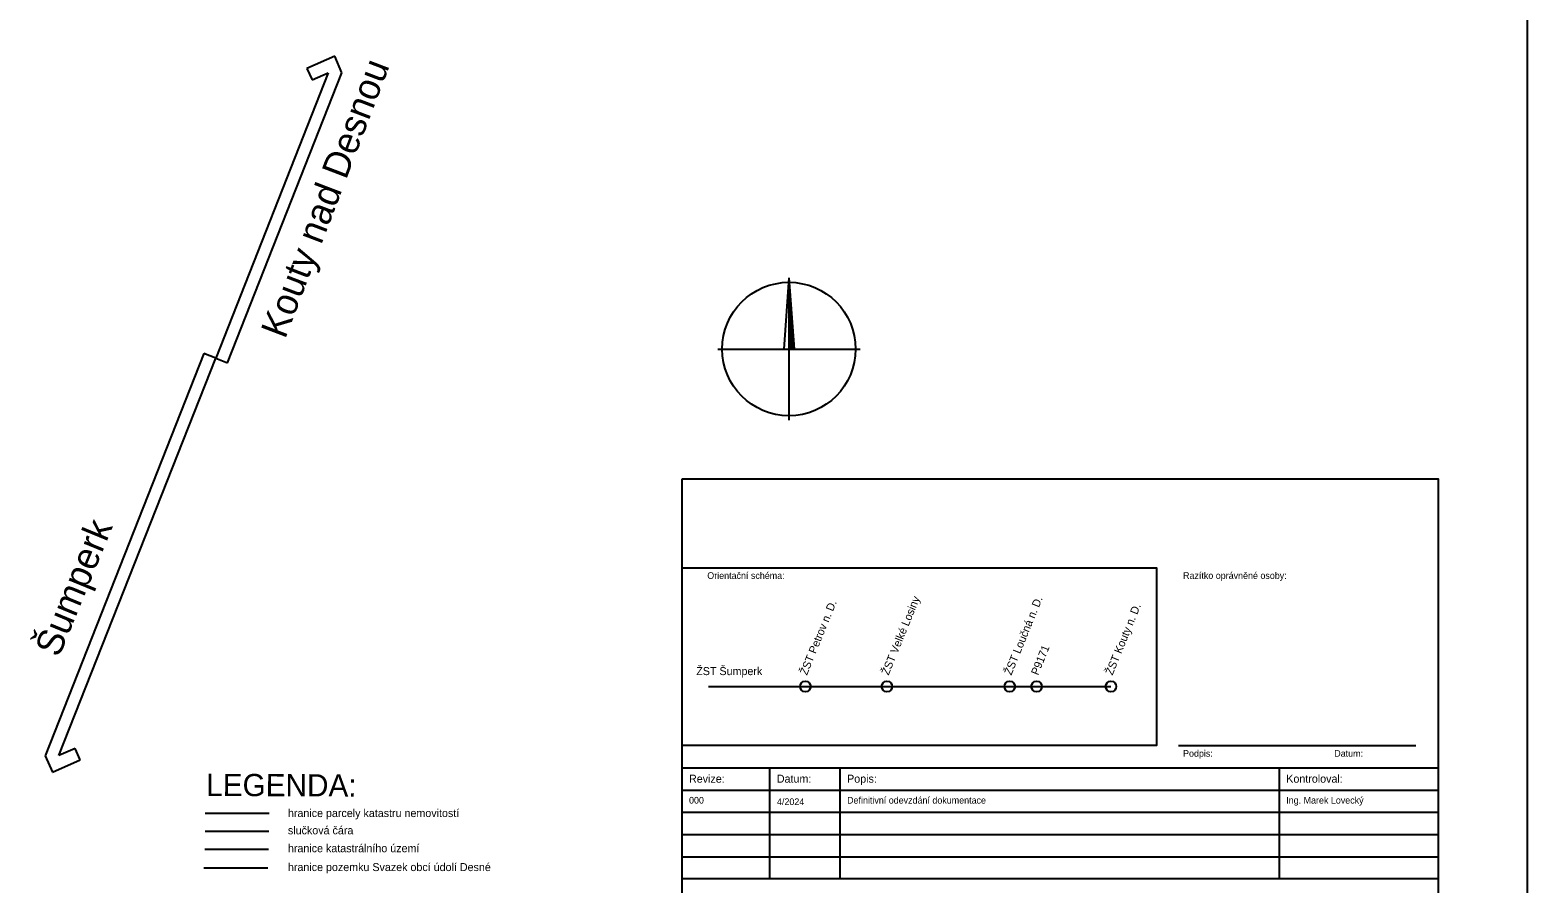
# Model space of a CAD drawing. Extents: x -553916 to -552953, y -1067470 to -1066637.
# Drawn here: x -553289.8 to -552953.1, y -1067224.2 to -1067032.3 of the extents above; entities that cross this region are included whole.
import ezdxf

# ---------------------------------------------------------------- set-up
doc = ezdxf.new("R2010")
doc.units = 0
for name, color, linetype in [('ROZPISKA', 7, 'Continuous'), ('Rozpiska_pola_3', 7, 'Continuous'), ('Rozpiska_pole_1', 7, 'Continuous'), ('Rozpiska_pole_2', 7, 'Continuous'), ('Rozpiska_pole_4', 7, 'Continuous'), ('Rozpiska_pole_6', 7, 'Continuous'), ('Rozpiska_pole_7', 7, 'Continuous'), ('Vrstva 1', 7, 'Continuous')]:
    doc.layers.add(name, color=color, linetype=linetype)

# ---------------------------------------------------------------- blocks, each defined once
blk = doc.blocks.new('_U2')
at = {"layer": 'Rozpiska_pola_3'}
blk.add_line((-2.6675, -1.82505), (2.6675, -1.82505), dxfattribs=at)
for s, p in [('Razítko oprávněné osoby:', (-2.5675, 1.92495)), ('Podpis:', (-2.5675, -2.07505)), ('Datum:', (0.8325, -2.07505))]:
    blk.add_text(s, height=0.15, dxfattribs=at).set_placement(p)
blk = doc.blocks.new('_U3')
at = {"layer": 'Rozpiska_pole_2'}
blk.add_lwpolyline([(-5.33255, 2.00005), (5.33245, 2.00005), (5.33245, -1.99995), (-5.33255, -1.99995)], close=True, dxfattribs=at)
blk.add_text('Orientační schéma:', height=0.15, dxfattribs=at).set_placement((-4.76755, 1.75005))

msp = doc.modelspace()

# ---------------------------------------------------------------- linework, layer by layer
at = {"layer": 'ROZPISKA'}
msp.add_lwpolyline([(-553137.18, -1067179.97), (-553046.68, -1067179.97)], dxfattribs=at)
for centre in [(-553115.39, -1067179.97), (-553097.05, -1067179.97), (-553069.44, -1067179.97), (-553063.4, -1067179.97), (-553046.68, -1067179.97), (-553046.68, -1067179.97), (-553046.68, -1067179.97), (-553046.68, -1067179.97)]:
    msp.add_circle(centre, 1.2, dxfattribs=at)
at = {"layer": 'Rozpiska_pole_1'}
msp.add_lwpolyline([(-553143.11, -1067133.27), (-552973.11, -1067133.27), (-552973.11, -1067393.27), (-553143.11, -1067393.27)], close=True, dxfattribs=at)
at = {"layer": 'Rozpiska_pole_4'}
for p, q in [((-553123.36, -1067223.27), (-553123.36, -1067198.27)), ((-553107.56, -1067223.27), (-553107.56, -1067198.27)), ((-553008.81, -1067223.27), (-553008.81, -1067198.27)), ((-553143.11, -1067203.27), (-552973.11, -1067203.27)), ((-553143.11, -1067208.27), (-552973.11, -1067208.27)), ((-553143.11, -1067213.27), (-552973.11, -1067213.27)), ((-553143.11, -1067218.27), (-552973.11, -1067218.27))]:
    msp.add_line(p, q, dxfattribs=at)
msp.add_lwpolyline([(-553143.11, -1067198.27), (-552973.11, -1067198.27), (-552973.11, -1067223.27), (-553143.11, -1067223.27)], close=True, dxfattribs=at)
at = {"layer": 'Vrstva 1'}
for p, q in [((-552953.11, -1066816.27), (-552953.11, -1067410.27)), ((-553221.23, -1067038.23), (-553227.51, -1067040.96)), ((-553219.64, -1067041.91), (-553221.23, -1067038.23)), ((-553222.7, -1067041.96), (-553248, -1067106.1)), ((-553245.37, -1067107.14), (-553219.64, -1067041.91)), ((-553227.51, -1067040.96), (-553226.33, -1067043.54)), ((-553226.33, -1067043.54), (-553222.7, -1067041.96)), ((-553119.1, -1067088.06), (-553120.25, -1067104.06)), ((-553119.1, -1067088.06), (-553117.93, -1067104.06)), ((-553119.1, -1067088.06), (-553119.1, -1067120.06)), ((-553119.01, -1067090.3), (-553118.03, -1067103.96)), ((-553118.97, -1067103.92), (-553119.01, -1067090.3)), ((-553118.94, -1067092.53), (-553118.14, -1067103.89)), ((-553118.87, -1067103.82), (-553118.94, -1067092.53)), ((-553118.83, -1067095.11), (-553118.24, -1067103.75)), ((-553118.8, -1067103.75), (-553118.83, -1067095.11)), ((-553118.73, -1067097.79), (-553118.35, -1067103.64)), ((-553118.69, -1067103.68), (-553118.73, -1067097.79)), ((-553135.1, -1067104.06), (-553103.1, -1067104.06)), ((-553117.93, -1067104.06), (-553118.97, -1067103.92)), ((-553118.03, -1067103.96), (-553118.87, -1067103.82)), ((-553118.14, -1067103.89), (-553118.8, -1067103.75)), ((-553118.24, -1067103.75), (-553118.69, -1067103.68)), ((-553118.59, -1067100.79), (-553118.45, -1067103.47)), ((-553118.59, -1067103.57), (-553118.59, -1067100.79)), ((-553118.35, -1067103.64), (-553118.59, -1067103.57)), ((-553250.64, -1067105.06), (-553286.33, -1067195.54)), ((-553283.26, -1067195.49), (-553248, -1067106.1)), ((-553248, -1067106.1), (-553250.64, -1067105.06)), ((-553248, -1067106.1), (-553245.37, -1067107.14)), ((-553279.59, -1067193.89), (-553283.26, -1067195.49)), ((-553278.46, -1067196.5), (-553279.59, -1067193.89)), ((-553286.33, -1067195.54), (-553284.73, -1067199.22)), ((-553284.73, -1067199.22), (-553278.46, -1067196.5)), ((-553250.34, -1067208.49), (-553236.01, -1067208.49)), ((-553250.35, -1067212.51), (-553236.02, -1067212.5)), ((-553250.47, -1067216.58), (-553236.14, -1067216.58)), ((-553250.64, -1067220.78), (-553236.31, -1067220.77))]:
    msp.add_line(p, q, dxfattribs=at)
msp.add_circle((-553119.1, -1067104.06), 15, dxfattribs=at)

# ---------------------------------------------------------------- block references
at = {"layer": 'Rozpiska_pola_3', "xscale": 10, "yscale": 10}
msp.add_blockref('_U2', (-553004.79, -1067175.02), dxfattribs=at)
at = {"layer": 'Rozpiska_pole_2', "xscale": 10, "yscale": 10}
msp.add_blockref('_U3', (-553089.78, -1067173.27), dxfattribs=at)

# ---------------------------------------------------------------- texts
at = {"layer": 'Rozpiska_pole_4'}
for s, height, p in [('Revize:', 1.8, (-553141.56, -1067201.61)), ('Datum:', 1.8, (-553121.81, -1067201.61)), ('Popis:', 1.8, (-553106.01, -1067201.61)), ('Kontroloval:', 1.8, (-553007.26, -1067201.61)), ('000', 1.5, (-553141.56, -1067206.31)), ('4/2024', 1.5, (-553121.78, -1067206.64)), ('Definitivní odevzdání dokumentace', 1.5, (-553106.01, -1067206.31)), ('Ing. Marek Lovecký', 1.5, (-553007.26, -1067206.31))]:
    msp.add_text(s, height=height, dxfattribs=at).set_placement(p)
at = {"layer": 'Rozpiska_pole_6'}
for s, p in [('hranice parcely katastru nemovitostí', (-553231.76, -1067209.34)), ('slučková čára', (-553231.76, -1067213.22)), ('hranice katastrálního území', (-553231.76, -1067217.25)), ('hranice pozemku Svazek obcí údolí Desné', (-553231.76, -1067221.49))]:
    msp.add_text(s, height=1.8, dxfattribs=at).set_placement(p)
at = {"layer": 'Rozpiska_pole_7'}
for s, p in [('ŽST Petrov n. D.', (-553115.05, -1067177.57)), ('ŽST Velké Losiny', (-553096.7, -1067177.57)), ('ŽST Loučná n. D.', (-553069.09, -1067177.57)), ('ŽST Kouty n. D.', (-553046.34, -1067177.57)), ('P9171', (-553063.06, -1067177.57))]:
    msp.add_text(s, height=1.8, rotation=67.8731, dxfattribs=at).set_placement(p)
msp.add_text('ŽST Šumperk', height=1.8, dxfattribs=at).set_placement((-553139.93, -1067177.41))
at = {"layer": 'Vrstva 1'}
for s, height, rotation, p in [('Kouty nad Desnou', 6, 69.0934, (-553232.39, -1067101.99)), ('Šumperk', 6, 67.6812, (-553283.27, -1067173.63)), ('LEGENDA:', 5, 359.7771, (-553250.14, -1067204.6))]:
    msp.add_text(s, height=height, rotation=rotation, dxfattribs=at).set_placement(p)

doc.saveas('drawing.dxf')
